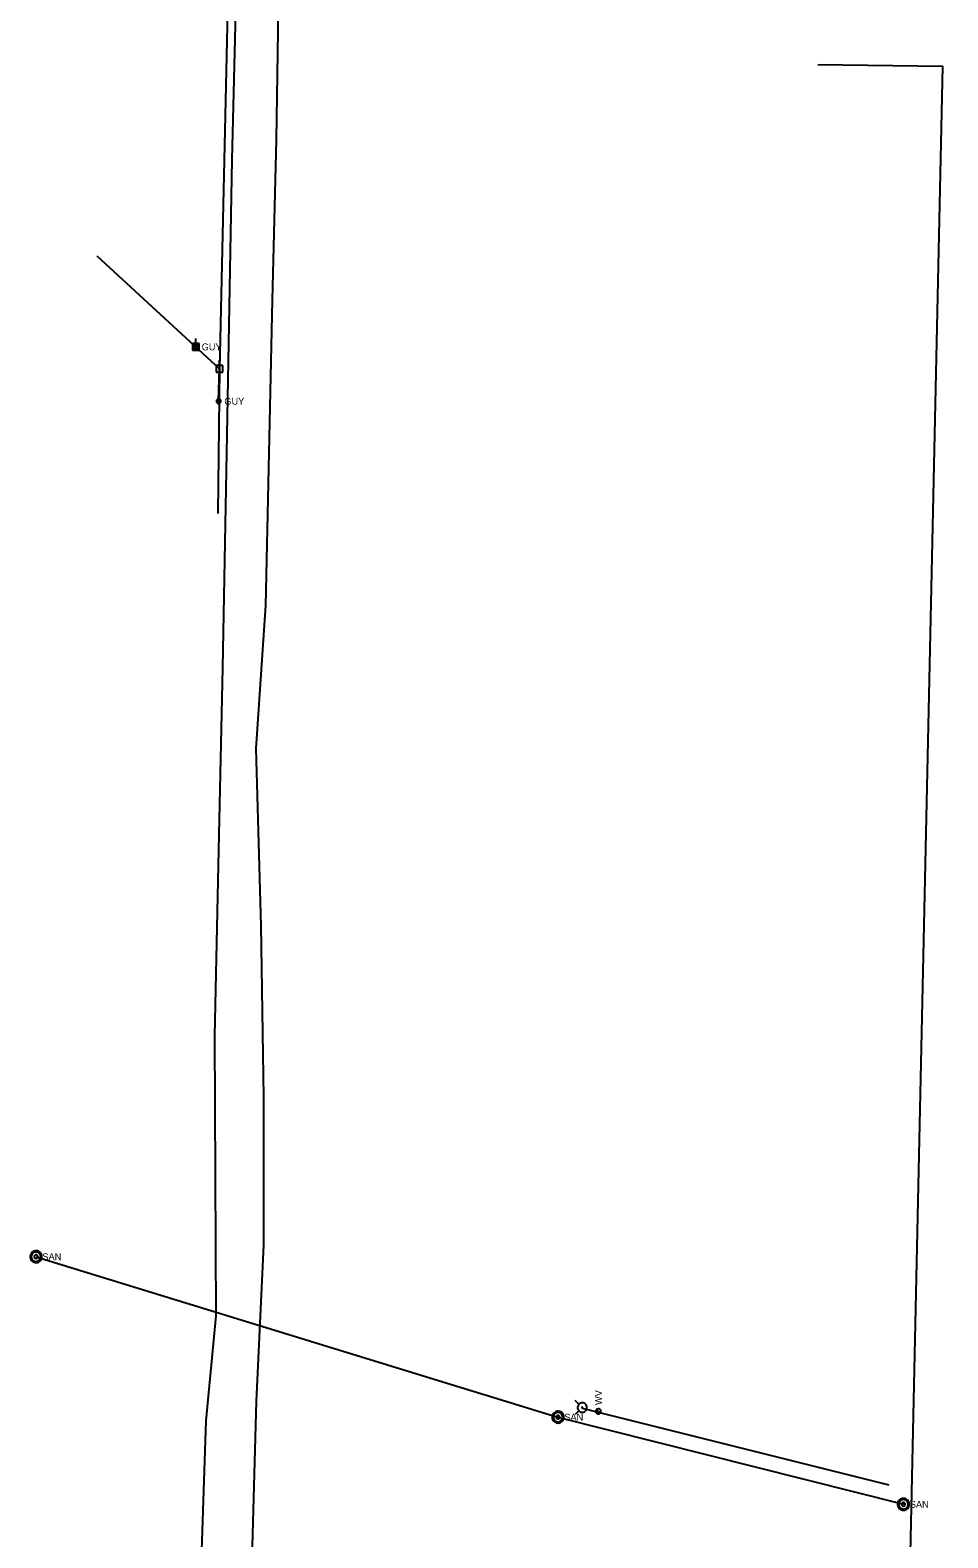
# Model space of a CAD drawing. Extents: x 596028 to 606371, y 330010 to 403088.
# Drawn here: x 604055 to 604568, y 342421 to 343265 of the extents above; entities that cross this region are included whole.
import ezdxf

# ---------------------------------------------------------------- set-up
doc = ezdxf.new("R2010")
doc.units = 0
for name, color, linetype in [('E_FTMS_Conduit', 7, 'Continuous'), ('E_UTL_EGuyWire', 7, 'Continuous'), ('E_UTL_EPowerPole', 7, 'Continuous'), ('E_UTL_FO_UG_QWEST', 7, 'Continuous'), ('E_UTL_Overhead', 7, 'Continuous'), ('E_UTL_SAN_MH', 7, 'Continuous'), ('E_UTL_SAN_UG', 7, 'Continuous'), ('E_UTL_W', 7, 'Continuous'), ('E_UTL_W_UG', 7, 'Continuous'), ('E_UTL_WHydrant', 7, 'Continuous')]:
    doc.layers.add(name, color=color, linetype=linetype)

msp = doc.modelspace()

# ---------------------------------------------------------------- linework, layer by layer
at = {"layer": 'E_FTMS_Conduit'}
msp.add_lwpolyline([(604179.23, 342409.96), (604181.78, 342497.97), (604185.88, 342585.2), (604185.82, 342667.88), (604184.34, 342763.9), (604181.59, 342862.8), (604186.96, 342942.75), (604188.82, 343028.25), (604190.64, 343113.59), (604192.94, 343203.35), (604194.17, 343288.51)], dxfattribs=at)
at = {"layer": 'E_UTL_EGuyWire'}
msp.add_line((604160.54, 343057.08), (604161.01, 343075.24), dxfattribs=at)
for points in [[(604149.15, 343087.47), (604149.12, 343087.71), (604149.06, 343087.94), (604148.94, 343088.16), (604148.79, 343088.35), (604148.61, 343088.51), (604148.4, 343088.63), (604148.17, 343088.71), (604147.93, 343088.75), (604147.68, 343088.74), (604147.44, 343088.68), (604147.22, 343088.58), (604147.02, 343088.43), (604146.86, 343088.26), (604146.72, 343088.05), (604146.63, 343087.83), (604146.59, 343087.59), (604146.59, 343087.34), (604146.63, 343087.1), (604146.72, 343086.88), (604146.86, 343086.67), (604147.02, 343086.5), (604147.22, 343086.35), (604147.44, 343086.25), (604147.68, 343086.19), (604147.93, 343086.18), (604148.17, 343086.22), (604148.4, 343086.3), (604148.61, 343086.42), (604148.79, 343086.58), (604148.94, 343086.77), (604149.06, 343086.99), (604149.12, 343087.22), (604149.15, 343087.47)], [(604148.02, 343087.47), (604148.02, 343087.5), (604148.01, 343087.52), (604148, 343087.55), (604147.98, 343087.58), (604147.96, 343087.6), (604147.93, 343087.61), (604147.9, 343087.62), (604147.87, 343087.63), (604147.84, 343087.62), (604147.81, 343087.62), (604147.78, 343087.6), (604147.76, 343087.59), (604147.74, 343087.56), (604147.72, 343087.54), (604147.71, 343087.51), (604147.7, 343087.48), (604147.7, 343087.45), (604147.71, 343087.42), (604147.72, 343087.39), (604147.74, 343087.37), (604147.76, 343087.34), (604147.78, 343087.33), (604147.81, 343087.31), (604147.84, 343087.31), (604147.87, 343087.3), (604147.9, 343087.31), (604147.93, 343087.32), (604147.96, 343087.33), (604147.98, 343087.35), (604148, 343087.38), (604148.01, 343087.41), (604148.02, 343087.43), (604148.02, 343087.47)], [(604161.82, 343057.08), (604161.8, 343057.32), (604161.73, 343057.55), (604161.62, 343057.77), (604161.46, 343057.96), (604161.28, 343058.12), (604161.07, 343058.24), (604160.84, 343058.32), (604160.6, 343058.36), (604160.35, 343058.35), (604160.12, 343058.29), (604159.89, 343058.19), (604159.7, 343058.04), (604159.53, 343057.87), (604159.4, 343057.66), (604159.3, 343057.44), (604159.26, 343057.2), (604159.26, 343056.95), (604159.3, 343056.71), (604159.4, 343056.49), (604159.53, 343056.28), (604159.7, 343056.11), (604159.89, 343055.96), (604160.12, 343055.86), (604160.35, 343055.8), (604160.6, 343055.79), (604160.84, 343055.83), (604161.07, 343055.91), (604161.28, 343056.03), (604161.46, 343056.19), (604161.62, 343056.38), (604161.73, 343056.6), (604161.8, 343056.83), (604161.82, 343057.08)], [(604160.7, 343057.08), (604160.69, 343057.11), (604160.68, 343057.13), (604160.67, 343057.16), (604160.65, 343057.19), (604160.63, 343057.21), (604160.6, 343057.22), (604160.57, 343057.23), (604160.54, 343057.24), (604160.51, 343057.23), (604160.48, 343057.23), (604160.46, 343057.21), (604160.43, 343057.2), (604160.41, 343057.17), (604160.39, 343057.15), (604160.38, 343057.12), (604160.38, 343057.09), (604160.38, 343057.06), (604160.38, 343057.03), (604160.39, 343057), (604160.41, 343056.98), (604160.43, 343056.95), (604160.46, 343056.94), (604160.48, 343056.92), (604160.51, 343056.92), (604160.54, 343056.91), (604160.57, 343056.92), (604160.6, 343056.93), (604160.63, 343056.94), (604160.65, 343056.96), (604160.67, 343056.99), (604160.68, 343057.02), (604160.69, 343057.04), (604160.7, 343057.08)]]:
    msp.add_lwpolyline(points, dxfattribs=at)
at = {"layer": 'E_UTL_EPowerPole'}
for points in [[(604149.68, 343089.31), (604145.99, 343089.31)], [(604145.99, 343089.31), (604145.99, 343085.62)], [(604147.83, 343089.31), (604147.83, 343092.22)], [(604149.68, 343085.62), (604149.68, 343089.31)], [(604145.99, 343085.62), (604149.68, 343085.62)], [(604148.1, 343087.47), (604148.1, 343087.51), (604148.09, 343087.55), (604148.06, 343087.59), (604148.04, 343087.63), (604148, 343087.66), (604147.96, 343087.68), (604147.92, 343087.7), (604147.88, 343087.7), (604147.83, 343087.7), (604147.79, 343087.69), (604147.74, 343087.67), (604147.71, 343087.65), (604147.68, 343087.61), (604147.65, 343087.57), (604147.64, 343087.53), (604147.63, 343087.49), (604147.63, 343087.44), (604147.64, 343087.4), (604147.65, 343087.36), (604147.68, 343087.32), (604147.71, 343087.28), (604147.74, 343087.26), (604147.79, 343087.24), (604147.83, 343087.23), (604147.88, 343087.23), (604147.92, 343087.23), (604147.96, 343087.25), (604148, 343087.27), (604148.04, 343087.3), (604148.06, 343087.34), (604148.09, 343087.38), (604148.1, 343087.42), (604148.1, 343087.47)], [(604162.82, 343077.08), (604159.13, 343077.08)], [(604159.13, 343077.08), (604159.13, 343073.39)], [(604159.13, 343073.39), (604162.82, 343073.39)], [(604161.25, 343075.24), (604161.24, 343075.28), (604161.23, 343075.33), (604161.21, 343075.37), (604161.18, 343075.4), (604161.15, 343075.43), (604161.11, 343075.45), (604161.07, 343075.47), (604161.02, 343075.48), (604160.98, 343075.47), (604160.93, 343075.46), (604160.89, 343075.44), (604160.85, 343075.42), (604160.82, 343075.39), (604160.8, 343075.35), (604160.78, 343075.31), (604160.77, 343075.26), (604160.77, 343075.22), (604160.78, 343075.17), (604160.8, 343075.13), (604160.82, 343075.09), (604160.85, 343075.06), (604160.89, 343075.03), (604160.93, 343075.01), (604160.98, 343075), (604161.02, 343075), (604161.07, 343075.01), (604161.11, 343075.02), (604161.15, 343075.04), (604161.18, 343075.07), (604161.21, 343075.11), (604161.23, 343075.15), (604161.24, 343075.19), (604161.25, 343075.24)], [(604160.98, 343077.08), (604160.98, 343079.99)], [(604162.82, 343073.39), (604162.82, 343077.08)]]:
    msp.add_lwpolyline(points, dxfattribs=at)
at = {"layer": 'E_UTL_FO_UG_QWEST'}
msp.add_lwpolyline([(604074.02, 341549.29), (604099.38, 341947.24), (604129.88, 341964.31), (604137.32, 341975.94), (604143.1, 342010.03), (604146.18, 342181.17), (604148.98, 342347.45), (604153.5, 342486.89), (604159.1, 342545.66), (604158.45, 342702.25), (604160.65, 342806.25), (604162.9, 342907.93), (604165.35, 343038.3), (604168.14, 343192.06), (604172.85, 343380.14)], dxfattribs=at)
at = {"layer": 'E_UTL_Overhead'}
msp.add_line((604165.72, 343285.6), (604161.01, 343075.24), dxfattribs=at)
for points in [[(604568.41, 341967.14), (604539.32, 342039.94), (604547.84, 342429.96), (604565.62, 343244.18), (604495.62, 343245.2)], [(604092.41, 343138.45), (604161.01, 343075.24), (604160.04, 342994.28)]]:
    msp.add_lwpolyline(points, dxfattribs=at)
at = {"layer": 'E_UTL_SAN_MH'}
for points in [[(604061.71, 342578.69), (604061.65, 342579.32), (604061.47, 342579.92), (604061.19, 342580.48), (604060.8, 342580.97), (604060.32, 342581.38), (604059.78, 342581.7), (604059.19, 342581.9), (604058.57, 342581.99), (604057.94, 342581.96), (604057.33, 342581.81), (604056.76, 342581.55), (604056.25, 342581.19), (604055.82, 342580.73), (604055.48, 342580.21), (604055.24, 342579.62), (604055.12, 342579.01), (604055.12, 342578.38), (604055.24, 342577.76), (604055.48, 342577.18), (604055.82, 342576.65), (604056.25, 342576.2), (604056.76, 342575.84), (604057.33, 342575.58), (604057.94, 342575.43), (604058.57, 342575.4), (604059.19, 342575.49), (604059.78, 342575.69), (604060.32, 342576.01), (604060.8, 342576.42), (604061.19, 342576.91), (604061.47, 342577.47), (604061.65, 342578.07), (604061.71, 342578.69)], [(604061.05, 342578.69), (604061, 342579.19), (604060.86, 342579.67), (604060.63, 342580.12), (604060.32, 342580.52), (604059.94, 342580.84), (604059.51, 342581.1), (604059.03, 342581.26), (604058.53, 342581.33), (604058.03, 342581.31), (604057.55, 342581.19), (604057.09, 342580.98), (604056.68, 342580.69), (604056.33, 342580.33), (604056.06, 342579.9), (604055.88, 342579.44), (604055.78, 342578.94), (604055.78, 342578.44), (604055.88, 342577.95), (604056.06, 342577.48), (604056.33, 342577.06), (604056.68, 342576.7), (604057.09, 342576.41), (604057.55, 342576.2), (604058.03, 342576.08), (604058.53, 342576.06), (604059.03, 342576.13), (604059.51, 342576.29), (604059.94, 342576.54), (604060.32, 342576.87), (604060.63, 342577.27), (604060.86, 342577.71), (604061, 342578.19), (604061.05, 342578.69)], [(604059.4, 342578.69), (604059.38, 342578.88), (604059.33, 342579.06), (604059.24, 342579.23), (604059.13, 342579.38), (604058.98, 342579.5), (604058.82, 342579.59), (604058.64, 342579.66), (604058.46, 342579.68), (604058.27, 342579.67), (604058.09, 342579.63), (604057.91, 342579.55), (604057.76, 342579.44), (604057.63, 342579.31), (604057.53, 342579.15), (604057.46, 342578.97), (604057.42, 342578.79), (604057.42, 342578.6), (604057.46, 342578.41), (604057.53, 342578.24), (604057.63, 342578.08), (604057.76, 342577.95), (604057.91, 342577.84), (604058.09, 342577.76), (604058.27, 342577.71), (604058.46, 342577.7), (604058.64, 342577.73), (604058.82, 342577.79), (604058.98, 342577.89), (604059.13, 342578.01), (604059.24, 342578.16), (604059.33, 342578.33), (604059.38, 342578.51), (604059.4, 342578.69)], [(604353.63, 342488.97), (604353.57, 342489.6), (604353.4, 342490.2), (604353.11, 342490.76), (604352.72, 342491.25), (604352.25, 342491.66), (604351.7, 342491.98), (604351.11, 342492.18), (604350.49, 342492.27), (604349.86, 342492.24), (604349.25, 342492.09), (604348.68, 342491.83), (604348.17, 342491.47), (604347.74, 342491.01), (604347.4, 342490.49), (604347.17, 342489.9), (604347.05, 342489.29), (604347.05, 342488.66), (604347.17, 342488.05), (604347.4, 342487.46), (604347.74, 342486.93), (604348.17, 342486.48), (604348.68, 342486.12), (604349.25, 342485.86), (604349.86, 342485.71), (604350.49, 342485.68), (604351.11, 342485.77), (604351.7, 342485.97), (604352.25, 342486.29), (604352.72, 342486.7), (604353.11, 342487.19), (604353.4, 342487.75), (604353.57, 342488.35), (604353.63, 342488.97)], [(604352.97, 342488.97), (604352.93, 342489.47), (604352.78, 342489.96), (604352.55, 342490.4), (604352.24, 342490.8), (604351.86, 342491.13), (604351.43, 342491.38), (604350.96, 342491.54), (604350.46, 342491.61), (604349.96, 342491.59), (604349.47, 342491.47), (604349.01, 342491.26), (604348.6, 342490.97), (604348.26, 342490.61), (604347.99, 342490.18), (604347.8, 342489.72), (604347.71, 342489.23), (604347.71, 342488.72), (604347.8, 342488.23), (604347.99, 342487.77), (604348.26, 342487.34), (604348.6, 342486.98), (604349.01, 342486.69), (604349.47, 342486.48), (604349.96, 342486.36), (604350.46, 342486.34), (604350.96, 342486.41), (604351.43, 342486.57), (604351.86, 342486.82), (604352.24, 342487.15), (604352.55, 342487.55), (604352.78, 342487.99), (604352.93, 342488.48), (604352.97, 342488.97)], [(604351.32, 342488.97), (604351.31, 342489.16), (604351.25, 342489.34), (604351.17, 342489.51), (604351.05, 342489.66), (604350.91, 342489.78), (604350.74, 342489.88), (604350.57, 342489.94), (604350.38, 342489.96), (604350.19, 342489.95), (604350.01, 342489.91), (604349.84, 342489.83), (604349.68, 342489.72), (604349.56, 342489.59), (604349.45, 342489.43), (604349.38, 342489.25), (604349.35, 342489.07), (604349.35, 342488.88), (604349.38, 342488.7), (604349.45, 342488.52), (604349.56, 342488.36), (604349.68, 342488.23), (604349.84, 342488.12), (604350.01, 342488.04), (604350.19, 342487.99), (604350.38, 342487.99), (604350.57, 342488.01), (604350.74, 342488.07), (604350.91, 342488.17), (604351.05, 342488.29), (604351.17, 342488.44), (604351.25, 342488.61), (604351.31, 342488.79), (604351.32, 342488.97)], [(604546.85, 342440.23), (604546.79, 342440.86), (604546.61, 342441.46), (604546.33, 342442.02), (604545.94, 342442.51), (604545.47, 342442.92), (604544.92, 342443.24), (604544.33, 342443.44), (604543.71, 342443.53), (604543.08, 342443.5), (604542.47, 342443.35), (604541.9, 342443.09), (604541.39, 342442.73), (604540.96, 342442.27), (604540.62, 342441.75), (604540.38, 342441.16), (604540.27, 342440.55), (604540.27, 342439.92), (604540.38, 342439.3), (604540.62, 342438.72), (604540.96, 342438.19), (604541.39, 342437.74), (604541.9, 342437.38), (604542.47, 342437.12), (604543.08, 342436.97), (604543.71, 342436.94), (604544.33, 342437.03), (604544.92, 342437.23), (604545.47, 342437.55), (604545.94, 342437.96), (604546.33, 342438.45), (604546.61, 342439.01), (604546.79, 342439.61), (604546.85, 342440.23)], [(604546.19, 342440.23), (604546.14, 342440.73), (604546, 342441.22), (604545.77, 342441.66), (604545.46, 342442.06), (604545.08, 342442.38), (604544.65, 342442.64), (604544.17, 342442.8), (604543.68, 342442.87), (604543.18, 342442.85), (604542.69, 342442.73), (604542.23, 342442.52), (604541.82, 342442.23), (604541.48, 342441.87), (604541.2, 342441.44), (604541.02, 342440.98), (604540.92, 342440.48), (604540.92, 342439.98), (604541.02, 342439.49), (604541.2, 342439.02), (604541.48, 342438.6), (604541.82, 342438.24), (604542.23, 342437.95), (604542.69, 342437.74), (604543.18, 342437.62), (604543.68, 342437.6), (604544.17, 342437.67), (604544.65, 342437.83), (604545.08, 342438.08), (604545.46, 342438.41), (604545.77, 342438.81), (604546, 342439.25), (604546.14, 342439.73), (604546.19, 342440.23)], [(604544.54, 342440.23), (604544.52, 342440.42), (604544.47, 342440.6), (604544.38, 342440.77), (604544.27, 342440.92), (604544.13, 342441.04), (604543.96, 342441.13), (604543.78, 342441.2), (604543.6, 342441.22), (604543.41, 342441.21), (604543.23, 342441.17), (604543.06, 342441.09), (604542.9, 342440.98), (604542.77, 342440.85), (604542.67, 342440.69), (604542.6, 342440.51), (604542.57, 342440.33), (604542.57, 342440.14), (604542.6, 342439.95), (604542.67, 342439.78), (604542.77, 342439.62), (604542.9, 342439.49), (604543.06, 342439.38), (604543.23, 342439.3), (604543.41, 342439.25), (604543.6, 342439.24), (604543.78, 342439.27), (604543.96, 342439.33), (604544.13, 342439.43), (604544.27, 342439.55), (604544.38, 342439.7), (604544.47, 342439.87), (604544.52, 342440.05), (604544.54, 342440.23)]]:
    msp.add_lwpolyline(points, dxfattribs=at)
at = {"layer": 'E_UTL_SAN_UG'}
for p, q in [((604058.41, 342578.69), (604350.33, 342488.97)), ((604350.33, 342488.97), (604543.55, 342440.23))]:
    msp.add_line(p, q, dxfattribs=at)
at = {"layer": 'E_UTL_W'}
for points in [[(604372.95, 342493.62), (604372.68, 342493.6), (604372.42, 342493.52), (604372.18, 342493.4), (604371.97, 342493.23), (604371.79, 342493.02), (604371.65, 342492.79), (604371.57, 342492.53), (604371.53, 342492.26), (604371.54, 342491.99), (604371.6, 342491.73), (604371.72, 342491.48), (604371.87, 342491.26), (604372.07, 342491.07), (604372.3, 342490.93), (604372.55, 342490.83), (604372.82, 342490.78), (604373.09, 342490.78), (604373.35, 342490.83), (604373.6, 342490.93), (604373.83, 342491.07), (604374.03, 342491.26), (604374.19, 342491.48), (604374.3, 342491.73), (604374.36, 342491.99), (604374.38, 342492.26), (604374.34, 342492.53), (604374.25, 342492.79), (604374.11, 342493.02), (604373.94, 342493.23), (604373.72, 342493.4), (604373.48, 342493.52), (604373.22, 342493.6), (604372.95, 342493.62)], [(604373.96, 342491.19), (604371.94, 342493.2)]]:
    msp.add_lwpolyline(points, dxfattribs=at)
at = {"layer": 'E_UTL_W_UG'}
msp.add_line((604363.85, 342494), (604535.32, 342451.1), dxfattribs=at)
at = {"layer": 'E_UTL_WHydrant'}
for points in [[(604362.1, 342496.18), (604359.96, 342498.32)], [(604362.1, 342492.51), (604359.96, 342490.37)], [(604363.94, 342496.96), (604363.44, 342496.92), (604362.96, 342496.78), (604362.52, 342496.55), (604362.13, 342496.24), (604361.8, 342495.86), (604361.55, 342495.43), (604361.39, 342494.96), (604361.32, 342494.47), (604361.34, 342493.97), (604361.46, 342493.48), (604361.67, 342493.03), (604361.96, 342492.62), (604362.32, 342492.28), (604362.74, 342492.01), (604363.2, 342491.83), (604363.69, 342491.73), (604364.19, 342491.73), (604364.68, 342491.83), (604365.14, 342492.01), (604365.56, 342492.28), (604365.92, 342492.62), (604366.21, 342493.03), (604366.42, 342493.48), (604366.54, 342493.97), (604366.56, 342494.47), (604366.49, 342494.96), (604366.32, 342495.43), (604366.08, 342495.86), (604365.75, 342496.24), (604365.36, 342496.55), (604364.91, 342496.78), (604364.44, 342496.92), (604363.94, 342496.96)], [(604363.94, 342494.54), (604363.9, 342494.54), (604363.86, 342494.53), (604363.83, 342494.51), (604363.8, 342494.49), (604363.78, 342494.46), (604363.76, 342494.43), (604363.74, 342494.39), (604363.74, 342494.35), (604363.74, 342494.31), (604363.75, 342494.28), (604363.77, 342494.24), (604363.79, 342494.21), (604363.81, 342494.18), (604363.85, 342494.16), (604363.88, 342494.15), (604363.92, 342494.14), (604363.96, 342494.14), (604364, 342494.15), (604364.03, 342494.16), (604364.06, 342494.18), (604364.09, 342494.21), (604364.11, 342494.24), (604364.13, 342494.28), (604364.14, 342494.31), (604364.14, 342494.35), (604364.13, 342494.39), (604364.12, 342494.43), (604364.1, 342494.46), (604364.08, 342494.49), (604364.05, 342494.51), (604364.01, 342494.53), (604363.98, 342494.54), (604363.94, 342494.54)]]:
    msp.add_lwpolyline(points, dxfattribs=at)

# ---------------------------------------------------------------- texts
at = {"layer": 'E_UTL_EGuyWire'}
for p in [(604151.07, 343085.54), (604163.74, 343055.15)]:
    msp.add_text('GUY', height=3.85, dxfattribs=at).set_placement(p)
at = {"layer": 'E_UTL_SAN_MH'}
for p in [(604061.97, 342576.75), (604353.9, 342487.03), (604547.12, 342438.29)]:
    msp.add_text('SAN', height=3.849, dxfattribs=at).set_placement(p)
at = {"layer": 'E_UTL_W'}
msp.add_text('WV', height=3.85, rotation=90, dxfattribs=at).set_placement((604374.88, 342495.76))

doc.saveas('drawing.dxf')
